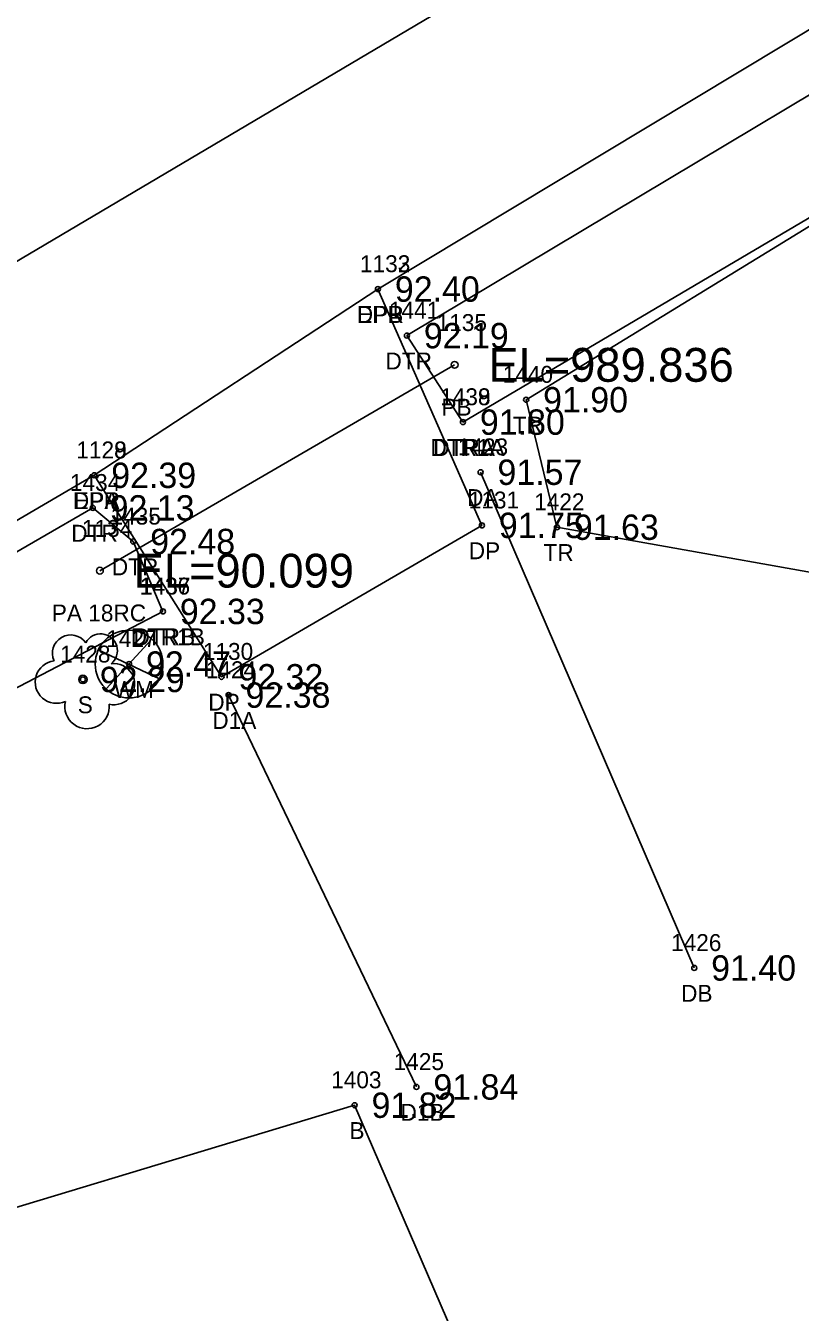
# Model space of a CAD drawing. Extents: x 2529517 to 2532038, y 935000 to 936944.
# Drawn here: x 2530988.7 to 2531034.4, y 935818.5 to 935894.6 of the extents above; entities that cross this region are included whole.
import ezdxf

# ---------------------------------------------------------------- set-up
doc = ezdxf.new("R2010")
doc.units = 0
for name, color, linetype in [('Default', 7, 'Continuous'), ('RD_EX_Bldg', 7, 'Continuous'), ('RD_EX_Bldg_txCode', 7, 'Continuous'), ('RD_EX_DR_Pipe', 7, 'Continuous'), ('RD_EX_DR_Pipe_txCode', 7, 'Continuous'), ('RD_EX_Driveway', 7, 'Continuous'), ('RD_EX_Driveway_txCode', 7, 'Continuous'), ('RD_EX_H2O', 7, 'Continuous'), ('RD_EX_H2O_txCode', 7, 'Continuous'), ('RD_EX_Road', 7, 'Continuous'), ('RD_EX_Road_txCode', 7, 'Continuous'), ('RD_EX_TX_Bldg_ELEV', 7, 'Continuous'), ('RD_EX_TX_Driveway_ELEV', 7, 'Continuous'), ('RD_EX_TX_H2O_ELEV', 7, 'Continuous'), ('RD_EX_TX_Road_ELEV', 7, 'Continuous'), ('RD_EX_TX_UT_ELEV', 7, 'Continuous'), ('RD_EX_TX_VEG_ELEV', 7, 'Continuous'), ('RD_EX_UT', 7, 'Continuous'), ('RD_EX_UT_txCode', 7, 'Continuous'), ('RD_EX_VEG', 7, 'Continuous'), ('RD_EX_VEG_txCode', 7, 'Continuous'), ('RD_HC_Cl', 7, 'Continuous'), ('RD_SMD_Locator', 7, 'Continuous'), ('RD_TX_Pipe_ElevEX', 7, 'Continuous')]:
    doc.layers.add(name, color=color, linetype=linetype)

msp = doc.modelspace()

# ---------------------------------------------------------------- linework, layer by layer
at = {"layer": 'Default'}
msp.add_line((2530557.048, 935625.341), (2531768.068, 936342.554), dxfattribs=at)
at = {"layer": 'RD_EX_Bldg'}
msp.add_lwpolyline([(2530978.74, 935821.888), (2531008.107, 935830.756), (2531025.169, 935791.245), (2530993.411, 935779.732), (2530978.74, 935821.888)], dxfattribs=at)
at = {"layer": 'RD_EX_DR_Pipe'}
msp.add_line((2530993.052, 935862.362), (2531014.018, 935874.533), dxfattribs=at)
at = {"layer": 'RD_EX_Driveway'}
for p, q in [((2531015.551, 935868.184), (2531028.182, 935838.872)), ((2531000.658, 935855.006), (2531011.762, 935831.837))]:
    msp.add_line(p, q, dxfattribs=at)
msp.add_lwpolyline([(2530992.723, 935868.002), (2531000.238, 935856.088), (2531015.632, 935865.042), (2531009.487, 935879.014)], dxfattribs=at)
at = {"layer": 'RD_EX_H2O'}
msp.add_line((2530970.94, 935846.455), (2530996.778, 935859.952), dxfattribs=at)
for points in [[(2531014.512, 935871.147), (2531011.198, 935876.261), (2531054.239, 935902.022), (2531084.907, 935920.574), (2531098.798, 935923.754), (2531103.295, 935929.494)], [(2531014.512, 935871.147), (2531057.214, 935896.364), (2531090.236, 935914.424), (2531102.959, 935919.079), (2531109.751, 935927.847)], [(2530970.94, 935846.455), (2530968.45, 935848.455), (2530967.561, 935851.576), (2530992.627, 935866.076), (2530995.026, 935864.088), (2530996.778, 935859.952)]]:
    msp.add_lwpolyline(points, dxfattribs=at)
at = {"layer": 'RD_EX_Road'}
msp.add_lwpolyline([(2530212.444, 935579.718), (2530312.608, 935580.142), (2530402.982, 935580.636), (2530451.057, 935579.535), (2530466.913, 935580.348), (2530487.453, 935583.291), (2530533.43, 935598.455), (2530580.282, 935625.084), (2530621.694, 935649.225), (2530704.615, 935698.354), (2530718.668, 935706.376), (2530795.45, 935752.358), (2530871.328, 935796.67), (2530882.405, 935803.04), (2530947.168, 935842.26), (2530966.001, 935852.419), (2530992.723, 935868.002), (2531009.487, 935879.014), (2531052.394, 935904.854), (2531090.884, 935928.231)], dxfattribs=at)
at = {"layer": 'RD_EX_UT'}
for p, q in [((2530993.422, 935855.383), (2530996.089, 935858.28)), ((2530992.941, 935857.679), (2530996.571, 935855.966))]:
    msp.add_line(p, q, dxfattribs=at)
msp.add_circle((2530994.774, 935856.841), 2, dxfattribs=at)
at = {"layer": 'RD_EX_VEG'}
msp.add_lwpolyline([(2531043.31, 935749.464), (2531037.626, 935787.205), (2531059.819, 935809.298), (2531081.939, 935810.853), (2531064.791, 935856.974), (2531020.066, 935864.933), (2531018.248, 935872.471), (2531057.214, 935896.364), (2531092.005, 935912.116), (2531117.324, 935919.344)], dxfattribs=at)
msp.add_circle((2530992.048, 935855.932), 0.25, dxfattribs=at)
for centre, radius, start, end in [((2530991.327, 935857.479), 1.084, 34.97629, 204.75602), ((2530993.093, 935857.634), 0.995, 308.76261, 152.04674), ((2530990.484, 935855.776), 1.257, 96.45179, 294.73401), ((2530993.888, 935855.652), 1.218, 256.56668, 98.10463), ((2530992.293, 935854.335), 1.318, 166.88266, 5.75893)]:
    msp.add_arc(centre, radius, start, end, dxfattribs=at)
at = {"layer": 'RD_HC_Cl'}
msp.add_line((2530557.048, 935625.341), (2531768.068, 936342.554), dxfattribs=at)
at = {"layer": 'RD_SMD_Locator'}
for centre, radius in [((2531009.487, 935879.014), 0.15), ((2531009.487, 935879.014), 0.15), ((2531011.198, 935876.261), 0.15), ((2531014.018, 935874.533), 0.2), ((2531018.248, 935872.471), 0.15), ((2531014.512, 935871.147), 0.15), ((2531014.512, 935871.147), 0.15), ((2530992.723, 935868.002), 0.15), ((2530992.723, 935868.002), 0.15), ((2531015.551, 935868.184), 0.15), ((2530992.627, 935866.076), 0.15), ((2531015.632, 935865.042), 0.15), ((2531020.066, 935864.933), 0.15), ((2530995.026, 935864.088), 0.15), ((2530993.052, 935862.362), 0.2), ((2530996.778, 935859.952), 0.15), ((2530996.778, 935859.952), 0.15), ((2530994.774, 935856.841), 0.15), ((2530992.048, 935855.932), 0.15), ((2531000.238, 935856.088), 0.15), ((2531000.658, 935855.006), 0.15), ((2531028.182, 935838.872), 0.15), ((2531011.762, 935831.837), 0.15), ((2531008.107, 935830.756), 0.15)]:
    msp.add_circle(centre, radius, dxfattribs=at)

# ---------------------------------------------------------------- texts
at = {"layer": 'RD_EX_Bldg_txCode'}
for s, p in [('1403', (2531006.721, 935831.756)), ('B', (2531007.8, 935828.756))]:
    msp.add_text(s, height=1, dxfattribs=at).set_placement(p)
at = {"layer": 'RD_EX_DR_Pipe_txCode'}
for s, p in [('1135', (2531012.955, 935876.533)), ('PB', (2531013.238, 935871.533)), ('1134', (2530991.989, 935864.362)), ('PA 18RC', (2530990.209, 935859.362))]:
    msp.add_text(s, height=1, dxfattribs=at).set_placement(p)
at = {"layer": 'RD_EX_Driveway_txCode'}
for s, p in [('1132', (2531008.424, 935880.014)), ('DPB', (2531008.235, 935877.014)), ('1129', (2530991.66, 935869.002)), ('1423', (2531014.205, 935869.184)), ('DPA', (2530991.456, 935866.002)), ('DA', (2531014.756, 935866.184)), ('1131', (2531014.853, 935866.042)), ('DP', (2531014.853, 935863.042)), ('1130', (2530999.136, 935857.088)), ('1424', (2530999.312, 935856.006)), ('DP', (2530999.459, 935854.088)), ('D1A', (2530999.697, 935853.006)), ('1426', (2531026.812, 935839.872)), ('DB', (2531027.403, 935836.872)), ('1425', (2531010.415, 935832.837)), ('D1B', (2531010.817, 935829.837))]:
    msp.add_text(s, height=1, dxfattribs=at).set_placement(p)
at = {"layer": 'RD_EX_H2O_txCode'}
for s, p in [('1441', (2531010.135, 935877.261)), ('DTR', (2531009.93, 935874.261)), ('1438', (2531013.166, 935872.147)), ('1439', (2531013.166, 935872.147)), ('DTR1A', (2531012.591, 935869.147)), ('DTRA', (2531012.756, 935869.147)), ('1434', (2530991.281, 935867.076)), ('1435', (2530993.68, 935865.088)), ('DTR', (2530991.36, 935864.076)), ('DTR', (2530993.759, 935862.088)), ('1436', (2530995.408, 935860.952)), ('1437', (2530995.432, 935860.952)), ('DTR1B', (2530994.873, 935857.952)), ('DTRB', (2530995.038, 935857.952))]:
    msp.add_text(s, height=1, dxfattribs=at).set_placement(p)
at = {"layer": 'RD_EX_Road_txCode'}
for s, p in [('1133', (2531008.424, 935880.014)), ('EPR', (2531008.259, 935877.014)), ('1128', (2530991.66, 935869.002)), ('EPR', (2530991.495, 935866.002))]:
    msp.add_text(s, height=1, dxfattribs=at).set_placement(p)
at = {"layer": 'RD_EX_TX_Bldg_ELEV'}
msp.add_text('91.82', height=1.5, dxfattribs=at).set_placement((2531009.107, 935830.006))
at = {"layer": 'RD_EX_TX_Driveway_ELEV'}
for s, p in [('92.40', (2531010.487, 935878.264)), ('92.39', (2530993.723, 935867.252)), ('91.57', (2531016.551, 935867.434)), ('91.75', (2531016.632, 935864.292)), ('92.32', (2531001.238, 935855.338)), ('92.38', (2531001.658, 935854.256)), ('91.40', (2531029.182, 935838.122)), ('91.84', (2531012.762, 935831.087))]:
    msp.add_text(s, height=1.5, dxfattribs=at).set_placement(p)
at = {"layer": 'RD_EX_TX_H2O_ELEV'}
for s, p in [('92.19', (2531012.198, 935875.511)), ('91.80', (2531015.512, 935870.397)), ('91.80', (2531015.512, 935870.397)), ('92.13', (2530993.627, 935865.326)), ('92.48', (2530996.026, 935863.338)), ('92.33', (2530997.778, 935859.202)), ('92.33', (2530997.778, 935859.202))]:
    msp.add_text(s, height=1.5, dxfattribs=at).set_placement(p)
at = {"layer": 'RD_EX_TX_Road_ELEV'}
for s, p in [('92.40', (2531010.487, 935878.264)), ('92.39', (2530993.723, 935867.252))]:
    msp.add_text(s, height=1.5, dxfattribs=at).set_placement(p)
at = {"layer": 'RD_EX_TX_UT_ELEV'}
msp.add_text('92.47', height=1.5, dxfattribs=at).set_placement((2530995.774, 935856.091))
at = {"layer": 'RD_EX_TX_VEG_ELEV'}
for s, p in [('91.90', (2531019.248, 935871.721)), ('91.63', (2531021.066, 935864.183)), ('92.29', (2530993.048, 935855.182))]:
    msp.add_text(s, height=1.5, dxfattribs=at).set_placement(p)
at = {"layer": 'RD_EX_UT_txCode'}
for s, p in [('1427', (2530993.428, 935857.841)), ('WM', (2530993.868, 935854.841))]:
    msp.add_text(s, height=1, dxfattribs=at).set_placement(p)
at = {"layer": 'RD_EX_VEG_txCode'}
for s, p in [('1440', (2531016.862, 935873.471)), ('TR', (2531017.453, 935870.471)), ('1422', (2531018.72, 935865.933)), ('TR', (2531019.271, 935862.933)), ('1428', (2530990.701, 935856.932)), ('S', (2530991.741, 935853.932))]:
    msp.add_text(s, height=1, dxfattribs=at).set_placement(p)
at = {"layer": 'RD_TX_Pipe_ElevEX'}
for s, p in [('EL=989.836', (2531016.018, 935873.533)), ('EL=90.099', (2530995.052, 935861.362))]:
    msp.add_text(s, height=2, dxfattribs=at).set_placement(p)

doc.saveas('drawing.dxf')
